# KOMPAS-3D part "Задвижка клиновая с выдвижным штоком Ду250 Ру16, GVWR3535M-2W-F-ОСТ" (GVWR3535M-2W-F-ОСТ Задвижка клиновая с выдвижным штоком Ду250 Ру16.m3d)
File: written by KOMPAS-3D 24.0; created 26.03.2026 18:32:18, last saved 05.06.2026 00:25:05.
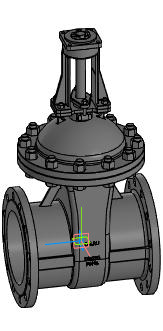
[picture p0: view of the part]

Document properties: Автор: R2D2; Полное имя файла: E:\Работа\Зайцев\GVWR3535M-2W-F-ОСТ Задвижка клиновая 30нж941нж DN.ru Ду50-200 Ру16\исходные данные\DN250\dn250\GVWR3535M-2W-F-ОСТ Задвижка клиновая с выдвижным штоком Ду250 Ру16.m3d

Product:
- Part/product: Задвижка клиновая с выдвижным штоком Ду250 Ру16  | designation GVWR3535M-2W-F-ОСТ
    Масса: 142.5
    Раздел спецификации: Прочие изделия
    Примечание: D040-09831

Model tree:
1. Операция без истории:1

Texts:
  GVWR3535M-2W-F-ОСТ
